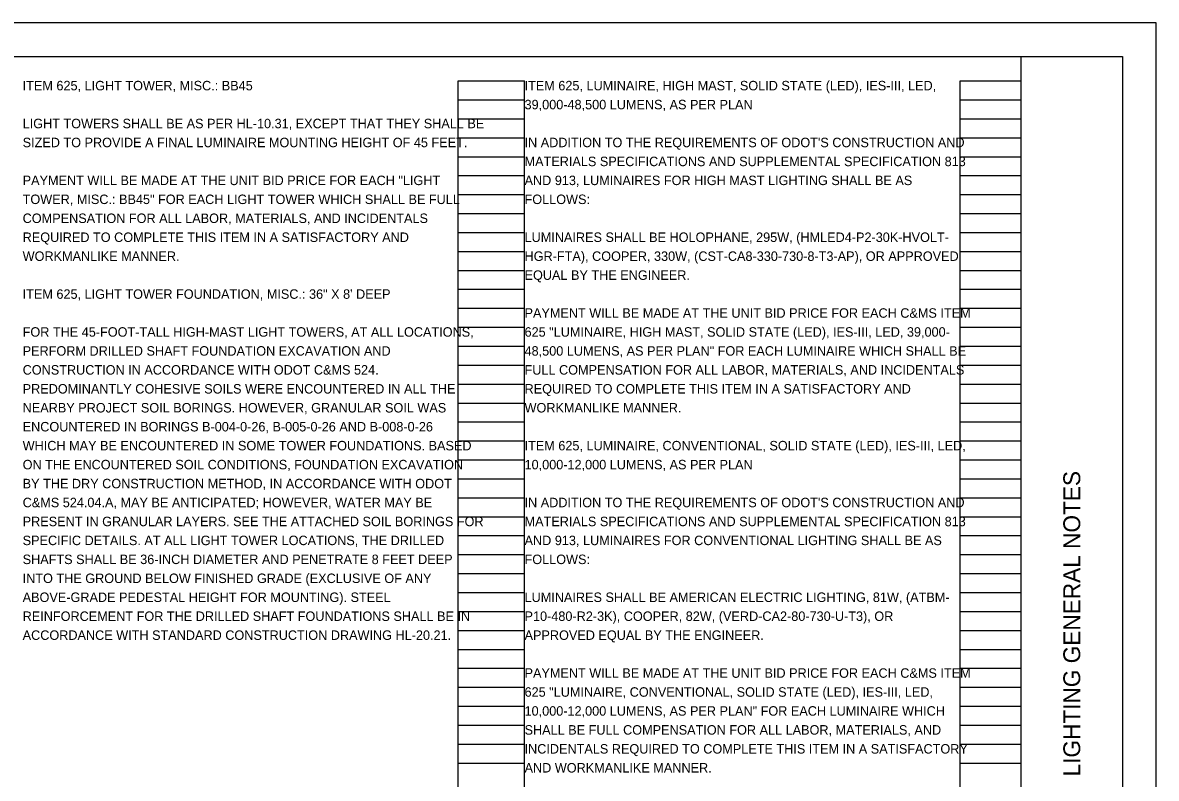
# Model space of a CAD drawing. Extents: x 0 to 34, y 0 to 22.
# Drawn here: x 17.24 to 34, y 10.83 to 22 of the extents above; entities that cross this region are included whole.
import ezdxf

# ---------------------------------------------------------------- set-up
doc = ezdxf.new("R2010")
doc.units = 0
for name, color, linetype in [('SH_Border', 7, 'Continuous'), ('SH_Cut_Line', 7, 'Continuous'), ('SH_Data', 7, 'Continuous'), ('SH_Text', 7, 'Continuous')]:
    doc.layers.add(name, color=color, linetype=linetype)

msp = doc.modelspace()

# ---------------------------------------------------------------- linework, layer by layer
at = {"layer": 'SH_Border'}
msp.add_line((32, 0.5), (32, 21.5), dxfattribs=at)
msp.add_lwpolyline([(1.5, 21.5), (33.5, 21.5), (33.5, 0.5), (1.5, 0.5)], close=True, dxfattribs=at)
at = {"layer": 'SH_Cut_Line'}
msp.add_lwpolyline([(0, 0), (34, 0), (34, 22), (0, 22)], close=True, dxfattribs=at)
at = {"layer": 'SH_Data'}
for p, q in [((23.68, 0.98), (23.68, 21.14)), ((23.68, 21.14), (24.66, 21.14)), ((24.66, 0.98), (24.66, 21.14)), ((31.1, 0.98), (31.1, 21.14)), ((31.1, 21.14), (32, 21.14)), ((32, 0.98), (32, 21.14)), ((23.68, 20.86), (24.66, 20.86)), ((31.1, 20.86), (32, 20.86)), ((23.68, 20.58), (24.66, 20.58)), ((31.1, 20.58), (32, 20.58)), ((23.68, 20.3), (24.66, 20.3)), ((31.1, 20.3), (32, 20.3)), ((23.68, 20.02), (24.66, 20.02)), ((31.1, 20.02), (32, 20.02)), ((23.68, 19.74), (24.66, 19.74)), ((31.1, 19.74), (32, 19.74)), ((23.68, 19.46), (24.66, 19.46)), ((31.1, 19.46), (32, 19.46)), ((23.68, 19.18), (24.66, 19.18)), ((31.1, 19.18), (32, 19.18)), ((23.68, 18.9), (24.66, 18.9)), ((31.1, 18.9), (32, 18.9)), ((23.68, 18.62), (24.66, 18.62)), ((31.1, 18.62), (32, 18.62)), ((23.68, 18.34), (24.66, 18.34)), ((31.1, 18.34), (32, 18.34)), ((23.68, 18.06), (24.66, 18.06)), ((31.1, 18.06), (32, 18.06)), ((23.68, 17.78), (24.66, 17.78)), ((31.1, 17.78), (32, 17.78)), ((23.68, 17.5), (24.66, 17.5)), ((31.1, 17.5), (32, 17.5)), ((23.68, 17.22), (24.66, 17.22)), ((31.1, 17.22), (32, 17.22)), ((23.68, 16.94), (24.66, 16.94)), ((31.1, 16.94), (32, 16.94)), ((23.68, 16.66), (24.66, 16.66)), ((31.1, 16.66), (32, 16.66)), ((23.68, 16.38), (24.66, 16.38)), ((31.1, 16.38), (32, 16.38)), ((23.68, 16.1), (24.66, 16.1)), ((31.1, 16.1), (32, 16.1)), ((23.68, 15.82), (24.66, 15.82)), ((31.1, 15.82), (32, 15.82)), ((23.68, 15.54), (24.66, 15.54)), ((31.1, 15.54), (32, 15.54)), ((23.68, 15.26), (24.66, 15.26)), ((31.1, 15.26), (32, 15.26)), ((23.68, 14.98), (24.66, 14.98)), ((31.1, 14.98), (32, 14.98)), ((23.68, 14.7), (24.66, 14.7)), ((31.1, 14.7), (32, 14.7)), ((23.68, 14.42), (24.66, 14.42)), ((31.1, 14.42), (32, 14.42)), ((23.68, 14.14), (24.66, 14.14)), ((31.1, 14.14), (32, 14.14)), ((23.68, 13.86), (24.66, 13.86)), ((31.1, 13.86), (32, 13.86)), ((23.68, 13.58), (24.66, 13.58)), ((31.1, 13.58), (32, 13.58)), ((23.68, 13.3), (24.66, 13.3)), ((31.1, 13.3), (32, 13.3)), ((23.68, 13.02), (24.66, 13.02)), ((31.1, 13.02), (32, 13.02)), ((23.68, 12.74), (24.66, 12.74)), ((31.1, 12.74), (32, 12.74)), ((23.68, 12.46), (24.66, 12.46)), ((31.1, 12.46), (32, 12.46)), ((23.68, 12.18), (24.66, 12.18)), ((31.1, 12.18), (32, 12.18)), ((23.68, 11.9), (24.66, 11.9)), ((31.1, 11.9), (32, 11.9)), ((23.68, 11.62), (24.66, 11.62)), ((31.1, 11.62), (32, 11.62)), ((23.68, 11.34), (24.66, 11.34)), ((31.1, 11.34), (32, 11.34)), ((23.68, 11.06), (24.66, 11.06)), ((31.1, 11.06), (32, 11.06))]:
    msp.add_line(p, q, dxfattribs=at)

# ---------------------------------------------------------------- texts
msp.add_text('LIGHTING GENERAL NOTES', height=0.25, rotation=90, dxfattribs=at).set_placement((32.875, 10.862))
at = {"layer": 'SH_Text'}
for s, p in [('ITEM 625, LIGHT TOWER, MISC.: BB45', (17.24, 21)), ('ITEM 625, LUMINAIRE, HIGH MAST, SOLID STATE (LED), IES-III, LED, ', (24.66, 21)), ('39,000-48,500 LUMENS, AS PER PLAN', (24.66, 20.72)), ('LIGHT TOWERS SHALL BE AS PER HL-10.31, EXCEPT THAT THEY SHALL BE ', (17.24, 20.44)), ('SIZED TO PROVIDE A FINAL LUMINAIRE MOUNTING HEIGHT OF 45 FEET.', (17.24, 20.16)), ("IN ADDITION TO THE REQUIREMENTS OF ODOT'S CONSTRUCTION AND ", (24.66, 20.16)), ('MATERIALS SPECIFICATIONS AND SUPPLEMENTAL SPECIFICATION 813 ', (24.66, 19.88)), ('PAYMENT WILL BE MADE AT THE UNIT BID PRICE FOR EACH "LIGHT ', (17.24, 19.6)), ('AND 913, LUMINAIRES FOR HIGH MAST LIGHTING SHALL BE AS ', (24.66, 19.6)), ('TOWER, MISC.: BB45" FOR EACH LIGHT TOWER WHICH SHALL BE FULL ', (17.24, 19.32)), ('FOLLOWS:', (24.66, 19.32)), ('COMPENSATION FOR ALL LABOR, MATERIALS, AND INCIDENTALS ', (17.24, 19.04)), ('REQUIRED TO COMPLETE THIS ITEM IN A SATISFACTORY AND ', (17.24, 18.76)), ('LUMINAIRES SHALL BE HOLOPHANE, 295W, (HMLED4-P2-30K-HVOLT-', (24.66, 18.76)), ('WORKMANLIKE MANNER.', (17.24, 18.48)), ('HGR-FTA), COOPER, 330W, (CST-CA8-330-730-8-T3-AP), OR APPROVED ', (24.66, 18.48)), ('EQUAL BY THE ENGINEER.', (24.66, 18.2)), ('ITEM 625, LIGHT TOWER FOUNDATION, MISC.: 36" X 8\' DEEP', (17.24, 17.92)), ('PAYMENT WILL BE MADE AT THE UNIT BID PRICE FOR EACH C&MS ITEM ', (24.66, 17.64)), ('FOR THE 45-FOOT-TALL HIGH-MAST LIGHT TOWERS, AT ALL LOCATIONS, ', (17.24, 17.36)), ('625 "LUMINAIRE, HIGH MAST, SOLID STATE (LED), IES-III, LED, 39,000-', (24.66, 17.36)), ('PERFORM DRILLED SHAFT FOUNDATION EXCAVATION AND ', (17.24, 17.08)), ('48,500 LUMENS, AS PER PLAN" FOR EACH LUMINAIRE WHICH SHALL BE ', (24.66, 17.08)), ('CONSTRUCTION IN ACCORDANCE WITH ODOT C&MS 524. ', (17.24, 16.8)), ('FULL COMPENSATION FOR ALL LABOR, MATERIALS, AND INCIDENTALS ', (24.66, 16.8)), ('PREDOMINANTLY COHESIVE SOILS WERE ENCOUNTERED IN ALL THE ', (17.24, 16.52)), ('REQUIRED TO COMPLETE THIS ITEM IN A SATISFACTORY AND ', (24.66, 16.52)), ('NEARBY PROJECT SOIL BORINGS. HOWEVER, GRANULAR SOIL WAS ', (17.24, 16.24)), ('WORKMANLIKE MANNER.', (24.66, 16.24)), ('ENCOUNTERED IN BORINGS B-004-0-26, B-005-0-26 AND B-008-0-26 ', (17.24, 15.96)), ('WHICH MAY BE ENCOUNTERED IN SOME TOWER FOUNDATIONS. BASED ', (17.24, 15.68)), ('ITEM 625, LUMINAIRE, CONVENTIONAL, SOLID STATE (LED), IES-III, LED, ', (24.66, 15.68)), ('ON THE ENCOUNTERED SOIL CONDITIONS, FOUNDATION EXCAVATION ', (17.24, 15.4)), ('10,000-12,000 LUMENS, AS PER PLAN', (24.66, 15.4)), ('BY THE DRY CONSTRUCTION METHOD, IN ACCORDANCE WITH ODOT ', (17.24, 15.12)), ('C&MS 524.04.A, MAY BE ANTICIPATED; HOWEVER, WATER MAY BE ', (17.24, 14.84)), ("IN ADDITION TO THE REQUIREMENTS OF ODOT'S CONSTRUCTION AND ", (24.66, 14.84)), ('PRESENT IN GRANULAR LAYERS. SEE THE ATTACHED SOIL BORINGS FOR ', (17.24, 14.56)), ('MATERIALS SPECIFICATIONS AND SUPPLEMENTAL SPECIFICATION 813 ', (24.66, 14.56)), ('SPECIFIC DETAILS. AT ALL LIGHT TOWER LOCATIONS, THE DRILLED ', (17.24, 14.28)), ('AND 913, LUMINAIRES FOR CONVENTIONAL LIGHTING SHALL BE AS ', (24.66, 14.28)), ('SHAFTS SHALL BE 36-INCH DIAMETER AND PENETRATE 8 FEET DEEP ', (17.24, 14)), ('FOLLOWS:', (24.66, 14)), ('INTO THE GROUND BELOW FINISHED GRADE (EXCLUSIVE OF ANY ', (17.24, 13.72)), ('ABOVE-GRADE PEDESTAL HEIGHT FOR MOUNTING). STEEL ', (17.24, 13.44)), ('LUMINAIRES SHALL BE AMERICAN ELECTRIC LIGHTING, 81W, (ATBM-', (24.66, 13.44)), ('REINFORCEMENT FOR THE DRILLED SHAFT FOUNDATIONS SHALL BE IN ', (17.24, 13.16)), ('P10-480-R2-3K), COOPER, 82W, (VERD-CA2-80-730-U-T3), OR ', (24.66, 13.16)), ('ACCORDANCE WITH STANDARD CONSTRUCTION DRAWING HL-20.21.', (17.24, 12.88)), ('APPROVED EQUAL BY THE ENGINEER.', (24.66, 12.88)), ('PAYMENT WILL BE MADE AT THE UNIT BID PRICE FOR EACH C&MS ITEM ', (24.66, 12.32)), ('625 "LUMINAIRE, CONVENTIONAL, SOLID STATE (LED), IES-III, LED, ', (24.66, 12.04)), ('10,000-12,000 LUMENS, AS PER PLAN" FOR EACH LUMINAIRE WHICH ', (24.66, 11.76)), ('SHALL BE FULL COMPENSATION FOR ALL LABOR, MATERIALS, AND ', (24.66, 11.48)), ('INCIDENTALS REQUIRED TO COMPLETE THIS ITEM IN A SATISFACTORY ', (24.66, 11.2)), ('AND WORKMANLIKE MANNER.', (24.66, 10.92))]:
    msp.add_text(s, height=0.14, dxfattribs=at).set_placement(p)

doc.saveas('drawing.dxf')
